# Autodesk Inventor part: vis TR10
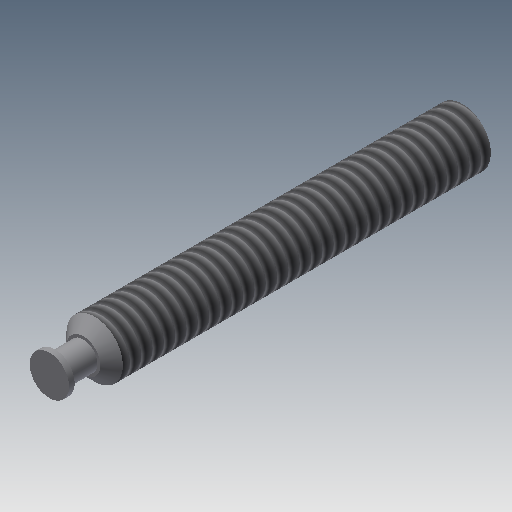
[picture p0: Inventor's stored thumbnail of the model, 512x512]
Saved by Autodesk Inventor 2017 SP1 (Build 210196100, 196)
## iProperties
Shininess: 64.0
Length Units: 11269
Angle Units: 11279
Time Units: 11290
Mass Units: 11283
Length Display Precision: 3
Angle Display Precision: 2
Compacted: True
Part Number: vis TR10
Document SubType Name: Modeling
Created: 2003-07
Material: Générique
Designer: trameau
Density: 1 g/cm^3
Appearance: Par défaut
Mass: 5.34437 g
Surface Area: 23.5817 cm^2
Volume: 5.34437 cm^3
Density: 0.0
Volumn: 0.0
Area: 0.0
PropertySet Name: Model Information
Control State: 0
Master: False
Checked Out: False
Author: trameau
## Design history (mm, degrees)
sketch "Esquisse1"
  geometry: C1 r 5 at (0, 0)
  constraints: 1 centre point
  dimensions: "d0" = 10 diameter of C1
extrude "Extrusion1" new body sketch "Esquisse1" distance "d1" = 65; taper "d2" = 0 deg
sketch "Esquisse2"
  geometry: C1 r 5 at (0, 0) reference; C2 r 5 at (0, 0)
  constraints: 1 centre point
  dimensions: "d3" = 10 diameter of C2
extrude "Extrusion2" join sketch "Esquisse2" distance "d4" = 2; taper "d5" = 0 deg
feature "Filetage1" dims "d6" = 65, "d7" = 0
sketch "Esquisse4"
  geometry: C1 r 5 at (0, 0) reference; C2 r 2.5 at (0, 0)
  constraints: 1 centre point
  dimensions: "d10" = 5 diameter of C2
extrude "Extrusion3" join sketch "Esquisse4" distance "d11" = 5; taper "d12" = 0 deg
chamfer "Chanfrein1" distance "d13" = 2; stored, may be unused: second distance "d14" = 2, angle "d18" = 45 deg
sketch "Esquisse5"
  geometry: C1 r 2.5 at (0, 0) reference; C2 r 3.5 at (0, 0)
  constraints: 1 centre point
  dimensions: "d15" = 7 diameter of C2
extrude "Extrusion4" join sketch "Esquisse5" distance "d16" = 1; taper "d17" = 0 deg
node "Solide1"
node "Corps solides"
node "Corps surfaciques"
